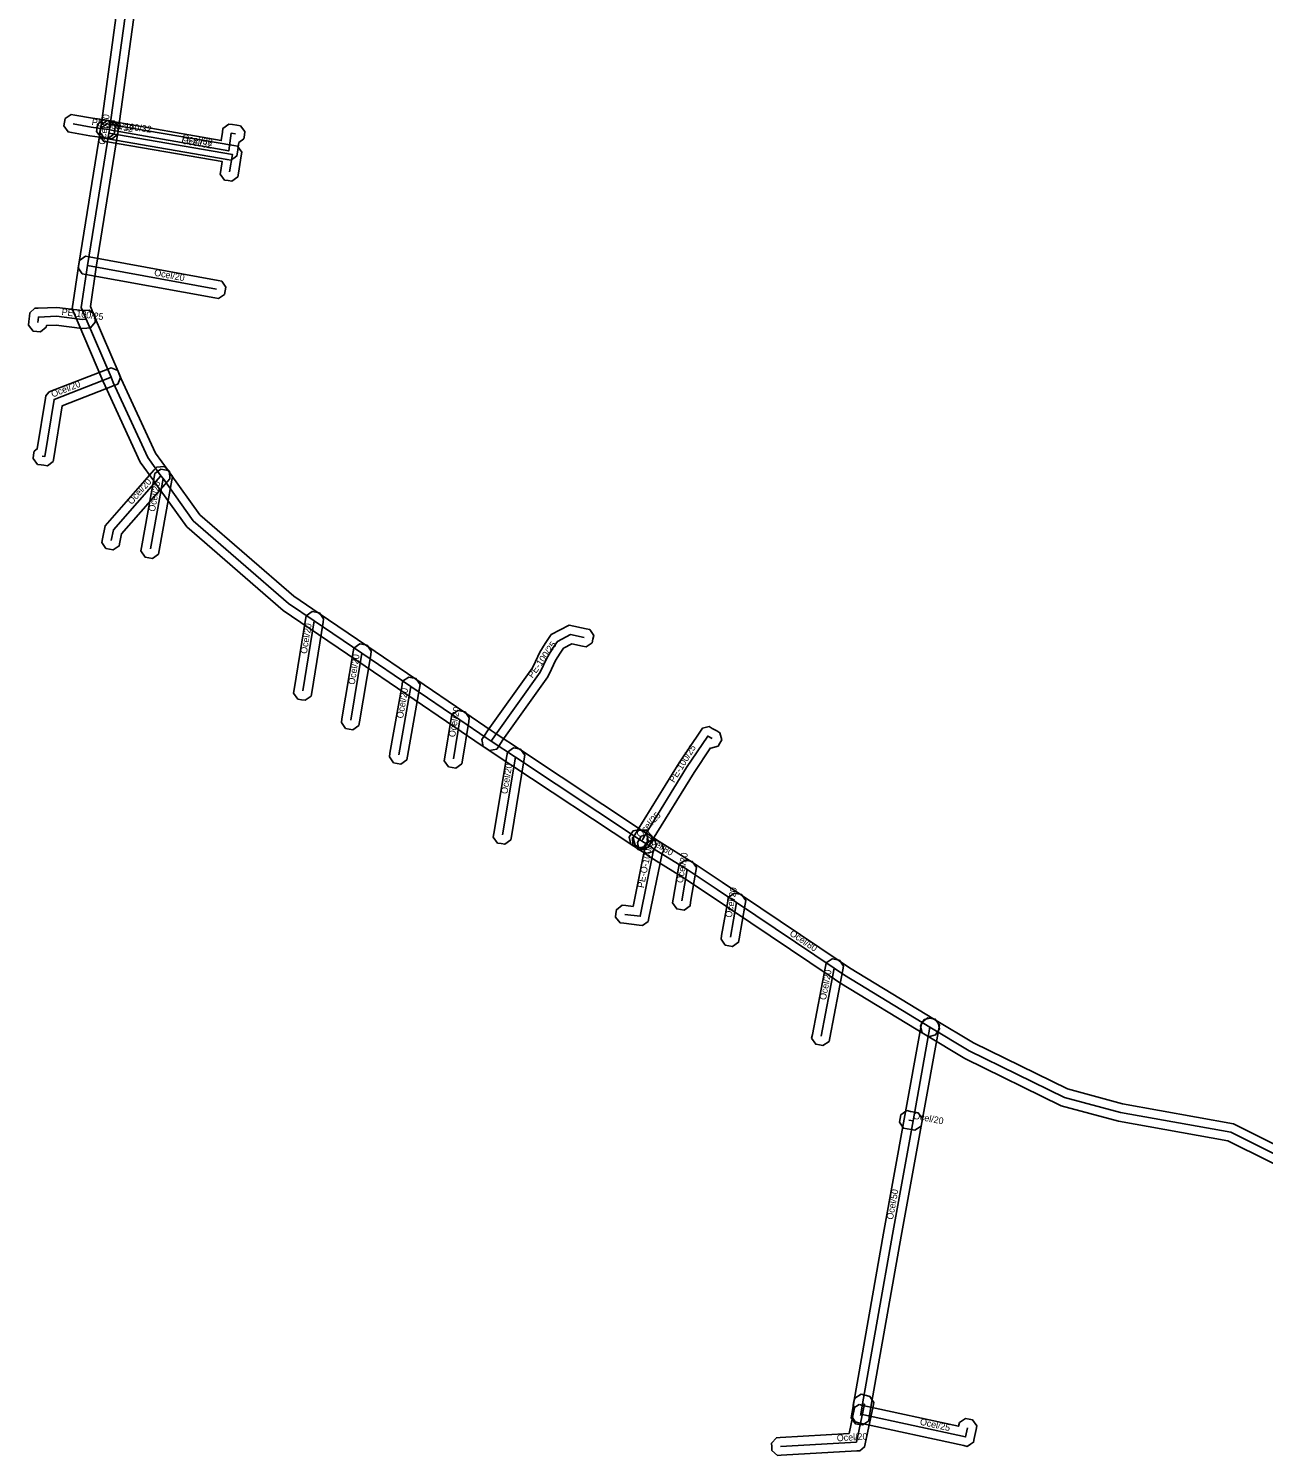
# Model space of a CAD drawing. Extents: x -569373 to -565022, y -1135090 to -1131496.
# Drawn here: x -566380.9 to -566241.6, y -1134005.2 to -1133844.4 of the extents above; entities that cross this region are included whole.
import ezdxf

# ---------------------------------------------------------------- set-up
doc = ezdxf.new("R2010")
doc.units = 0
for name, color, linetype in [('1', 7, 'Continuous'), ('24', 7, 'Continuous'), ('30', 7, 'Continuous')]:
    doc.layers.add(name, color=color, linetype=linetype)

msp = doc.modelspace()

# ---------------------------------------------------------------- linework, layer by layer
at = {"layer": '1'}
for points in [[(-566368.68, -1133840.941), (-566370.743, -1133855.926), (-566370.756, -1133855.988), (-566370.813, -1133856.339), (-566373.212, -1133871.254), (-566373.879, -1133875.691), (-566373.436, -1133876.743), (-566370.63, -1133883.289), (-566370.395, -1133883.846), (-566366.532, -1133892.224), (-566365.12, -1133894.184), (-566364.88, -1133894.514), (-566361.536, -1133899.161), (-566350.939, -1133908.356), (-566348.077, -1133910.301), (-566342.704, -1133913.951), (-566337.202, -1133917.689), (-566331.654, -1133921.459), (-566328.686, -1133923.475), (-566328.131, -1133923.853), (-566325.395, -1133925.664), (-566311.528, -1133934.846), (-566311.183, -1133935.075), (-566311.017, -1133935.887), (-566311.246, -1133936.232), (-566311.475, -1133936.577), (-566312.287, -1133936.743), (-566312.632, -1133936.514), (-566326.499, -1133927.332), (-566329.245, -1133925.513), (-566329.81, -1133925.129), (-566332.778, -1133923.113), (-566338.326, -1133919.343), (-566343.828, -1133915.605), (-566349.201, -1133911.955), (-566352.161, -1133909.944), (-566363.024, -1133900.519), (-566366.5, -1133895.686), (-566366.74, -1133895.356), (-566368.268, -1133893.236), (-566372.225, -1133884.654), (-566372.47, -1133884.071), (-566375.276, -1133877.525), (-566375.941, -1133875.949), (-566375.188, -1133870.946), (-566372.787, -1133856.021), (-566372.724, -1133855.632), (-566372.717, -1133855.594), (-566370.66, -1133840.659)], [(-566236.486, -1133974.254), (-566245.637, -1133969.709), (-566257.979, -1133967.497), (-566264.434, -1133965.75), (-566275.288, -1133960.44), (-566279.744, -1133957.768), (-566280.099, -1133957.555), (-566280.301, -1133956.751), (-566280.088, -1133956.396), (-566279.875, -1133956.041), (-566279.071, -1133955.839), (-566278.716, -1133956.052), (-566274.332, -1133958.68), (-566263.726, -1133963.87), (-566257.541, -1133965.543), (-566245.003, -1133967.791), (-566235.954, -1133972.286)]]:
    msp.add_lwpolyline(points, dxfattribs=at)
for points in [[(-566376.053, -1133854.063), (-566375.645, -1133854.135), (-566373.634, -1133854.492), (-566371.993, -1133854.719), (-566371.583, -1133854.776), (-566371.082, -1133855.437), (-566371.139, -1133855.847), (-566371.196, -1133856.257), (-566371.857, -1133856.758), (-566372.267, -1133856.701), (-566373.946, -1133856.468), (-566375.995, -1133856.105), (-566376.403, -1133856.033), (-566376.877, -1133855.353), (-566376.805, -1133854.945), (-566376.733, -1133854.537)], [(-566372.417, -1133854.667), (-566372.006, -1133854.718), (-566371.606, -1133854.768), (-566371.195, -1133854.819), (-566370.687, -1133855.473), (-566370.738, -1133855.884), (-566370.789, -1133856.295), (-566371.443, -1133856.803), (-566371.854, -1133856.752), (-566372.254, -1133856.702), (-566372.665, -1133856.651), (-566373.173, -1133855.997), (-566373.122, -1133855.586), (-566373.071, -1133855.175)], [(-566372.04, -1133855.124), (-566371.632, -1133855.194), (-566357.692, -1133857.574), (-566357.286, -1133857.643), (-566356.807, -1133858.314), (-566356.873, -1133858.72), (-566357.193, -1133860.69), (-566357.259, -1133861.099), (-566357.931, -1133861.583), (-566358.34, -1133861.517), (-566358.749, -1133861.451), (-566359.233, -1133860.779), (-566359.167, -1133860.37), (-566359.006, -1133859.379), (-566371.968, -1133857.166), (-566372.376, -1133857.096), (-566372.856, -1133856.42), (-566372.786, -1133856.012), (-566372.716, -1133855.604)], [(-566356.577, -1133856.809), (-566357.149, -1133857.24), (-566357.3, -1133858.31), (-566357.359, -1133858.73), (-566357.702, -1133858.979), (-566358.045, -1133859.228), (-566358.463, -1133859.155), (-566371.913, -1133856.795), (-566372.321, -1133856.723), (-566372.797, -1133856.045), (-566372.725, -1133855.637), (-566372.653, -1133855.229), (-566371.975, -1133854.753), (-566371.567, -1133854.825), (-566359.135, -1133857.006), (-566359, -1133856.05), (-566358.942, -1133855.64), (-566358.281, -1133855.142), (-566357.871, -1133855.2), (-566357.371, -1133855.27), (-566356.961, -1133855.327), (-566356.462, -1133855.989), (-566356.52, -1133856.399)], [(-566359.432, -1133874.819), (-566359.84, -1133874.744), (-566374.38, -1133872.084), (-566374.788, -1133872.009), (-566375.259, -1133871.328), (-566375.184, -1133870.92), (-566375.109, -1133870.512), (-566374.428, -1133870.041), (-566374.02, -1133870.116), (-566359.48, -1133872.776), (-566359.072, -1133872.851), (-566358.601, -1133873.532), (-566358.676, -1133873.94), (-566358.751, -1133874.348)], [(-566377.732, -1133877.812), (-566378.846, -1133877.856), (-566378.868, -1133878.047), (-566379.517, -1133878.562), (-566379.928, -1133878.514), (-566380.339, -1133878.466), (-566380.854, -1133877.817), (-566380.806, -1133877.406), (-566380.733, -1133876.775), (-566380.691, -1133876.408), (-566380.148, -1133875.905), (-566379.779, -1133875.891), (-566377.648, -1133875.808), (-566374.77, -1133876.165), (-566374.439, -1133876.137), (-566374.026, -1133876.103), (-566373.393, -1133876.638), (-566373.359, -1133877.051), (-566373.325, -1133877.464), (-566373.86, -1133878.097), (-566374.273, -1133878.131), (-566374.81, -1133878.175)], [(-566380.236, -1133892.018), (-566379.875, -1133891.741), (-566378.957, -1133886.022), (-566378.915, -1133885.759), (-566378.581, -1133885.345), (-566378.333, -1133885.248), (-566371.913, -1133882.748), (-566371.527, -1133882.598), (-566370.768, -1133882.931), (-566370.618, -1133883.317), (-566370.468, -1133883.703), (-566370.801, -1133884.462), (-566371.187, -1133884.612), (-566377.073, -1133886.904), (-566378.013, -1133892.758), (-566378.077, -1133893.16), (-566378.729, -1133893.645), (-566379.132, -1133893.591), (-566379.432, -1133893.551), (-566379.842, -1133893.496), (-566380.346, -1133892.838), (-566380.291, -1133892.428)], [(-566372.591, -1133902.281), (-566372.511, -1133901.875), (-566372.219, -1133900.401), (-566366.681, -1133894.109), (-566366.407, -1133893.798), (-566365.58, -1133893.746), (-566365.269, -1133894.019), (-566364.958, -1133894.293), (-566364.906, -1133895.12), (-566365.179, -1133895.431), (-566370.361, -1133901.319), (-566370.549, -1133902.265), (-566370.63, -1133902.671), (-566371.319, -1133903.131), (-566371.725, -1133903.051), (-566372.131, -1133902.97)], [(-566368.178, -1133903.25), (-566368.104, -1133902.842), (-566366.674, -1133894.922), (-566366.6, -1133894.514), (-566365.92, -1133894.042), (-566365.512, -1133894.116), (-566365.104, -1133894.19), (-566364.632, -1133894.87), (-566364.706, -1133895.278), (-566366.136, -1133903.198), (-566366.21, -1133903.606), (-566366.89, -1133904.078), (-566367.298, -1133904.004), (-566367.706, -1133903.93)], [(-566350.973, -1133919.269), (-566350.907, -1133918.86), (-566349.626, -1133910.968), (-566349.56, -1133910.559), (-566348.888, -1133910.075), (-566348.479, -1133910.141), (-566348.07, -1133910.207), (-566347.586, -1133910.879), (-566347.652, -1133911.288), (-566348.933, -1133919.18), (-566348.999, -1133919.589), (-566349.671, -1133920.073), (-566350.08, -1133920.007), (-566350.489, -1133919.941)], [(-566329.751, -1133924.48), (-566329.524, -1133924.134), (-566329.045, -1133923.405), (-566324.045, -1133916.401), (-566323.713, -1133915.699), (-566323.211, -1133914.654), (-566322.621, -1133913.679), (-566321.923, -1133912.657), (-566319.893, -1133911.608), (-566317.996, -1133912.006), (-566317.59, -1133912.091), (-566317.137, -1133912.785), (-566317.222, -1133913.19), (-566317.307, -1133913.596), (-566318.001, -1133914.049), (-566318.406, -1133913.964), (-566319.607, -1133913.712), (-566320.557, -1133914.203), (-566320.939, -1133914.761), (-566321.449, -1133915.606), (-566321.907, -1133916.561), (-566322.315, -1133917.419), (-566327.395, -1133924.535), (-566327.852, -1133925.232), (-566328.079, -1133925.578), (-566328.891, -1133925.746), (-566329.237, -1133925.519), (-566329.583, -1133925.292)], [(-566345.584, -1133922.573), (-566345.516, -1133922.165), (-566344.252, -1133914.613), (-566344.184, -1133914.205), (-566343.509, -1133913.724), (-566343.101, -1133913.792), (-566342.693, -1133913.86), (-566342.212, -1133914.535), (-566342.28, -1133914.943), (-566343.544, -1133922.495), (-566343.612, -1133922.903), (-566344.287, -1133923.384), (-566344.695, -1133923.316), (-566345.103, -1133923.248)], [(-566340.177, -1133926.434), (-566340.105, -1133926.026), (-566338.749, -1133918.342), (-566338.677, -1133917.934), (-566337.998, -1133917.459), (-566337.59, -1133917.531), (-566337.182, -1133917.603), (-566336.707, -1133918.282), (-566336.779, -1133918.69), (-566338.135, -1133926.374), (-566338.207, -1133926.782), (-566338.886, -1133927.257), (-566339.294, -1133927.185), (-566339.702, -1133927.113)], [(-566333.984, -1133926.908), (-566333.917, -1133926.499), (-566333.203, -1133922.125), (-566333.136, -1133921.716), (-566332.464, -1133921.232), (-566332.055, -1133921.299), (-566331.646, -1133921.366), (-566331.162, -1133922.038), (-566331.229, -1133922.447), (-566331.943, -1133926.821), (-566332.01, -1133927.23), (-566332.682, -1133927.714), (-566333.091, -1133927.647), (-566333.5, -1133927.58)], [(-566303.924, -1133925.463), (-566303.972, -1133925.435), (-566305.829, -1133928.201), (-566310.52, -1133935.811), (-566310.752, -1133936.216), (-566310.957, -1133936.576), (-566311.756, -1133936.793), (-566312.116, -1133936.588), (-566312.476, -1133936.383), (-566312.693, -1133935.584), (-566312.488, -1133935.224), (-566312.24, -1133934.789), (-566307.511, -1133927.119), (-566305.11, -1133923.543), (-566304.89, -1133923.215), (-566304.12, -1133923.037), (-566303.778, -1133923.235), (-566303.278, -1133923.525), (-566302.92, -1133923.733), (-566302.707, -1133924.534), (-566302.915, -1133924.892), (-566303.123, -1133925.25)], [(-566328.464, -1133935.483), (-566328.396, -1133935.075), (-566326.933, -1133926.333), (-566326.865, -1133925.925), (-566326.19, -1133925.444), (-566325.782, -1133925.512), (-566325.374, -1133925.58), (-566324.893, -1133926.255), (-566324.961, -1133926.663), (-566326.424, -1133935.405), (-566326.492, -1133935.813), (-566327.167, -1133936.294), (-566327.575, -1133936.226), (-566327.983, -1133936.158)], [(-566311.885, -1133934.615), (-566311.537, -1133934.84), (-566311.203, -1133935.057), (-566310.619, -1133935.423), (-566310.268, -1133935.643), (-566310.083, -1133936.45), (-566310.303, -1133936.801), (-566310.523, -1133937.152), (-566311.33, -1133937.337), (-566311.681, -1133937.117), (-566312.277, -1133936.743), (-566312.623, -1133936.52), (-566312.971, -1133936.295), (-566313.145, -1133935.485), (-566312.92, -1133935.137), (-566312.695, -1133934.789)], [(-566312.756, -1133935.526), (-566312.62, -1133935.379), (-566312.62, -1133935.306), (-566312.034, -1133934.72), (-566311.62, -1133934.72), (-566311.206, -1133934.72), (-566310.62, -1133935.306), (-566310.62, -1133935.72), (-566310.62, -1133936.161), (-566311.005, -1133936.578), (-566311.286, -1133936.882), (-566312.114, -1133936.916), (-566312.418, -1133936.635), (-566312.722, -1133936.354)], [(-566309.25, -1133936.989), (-566309.434, -1133937.295), (-566309.441, -1133937.33), (-566310.92, -1133944.599), (-566310.998, -1133944.98), (-566311.627, -1133945.438), (-566312.014, -1133945.393), (-566313.754, -1133945.193), (-566314.166, -1133945.146), (-566314.681, -1133944.497), (-566314.633, -1133944.086), (-566314.586, -1133943.674), (-566313.937, -1133943.159), (-566313.526, -1133943.207), (-566312.697, -1133943.302), (-566311.401, -1133936.93), (-566311.325, -1133936.562), (-566311.177, -1133936.316), (-566310.964, -1133935.961), (-566310.161, -1133935.76), (-566309.806, -1133935.973), (-566309.451, -1133936.186)], [(-566279.396, -1133957.979), (-566279.75, -1133957.764), (-566289.389, -1133951.893), (-566290.587, -1133951.091), (-566301.607, -1133943.691), (-566303.786, -1133942.231), (-566307.142, -1133939.99), (-566310.875, -1133937.663), (-566311.332, -1133937.338), (-566311.684, -1133937.115), (-566312.034, -1133936.894), (-566312.217, -1133936.086), (-566311.995, -1133935.736), (-566311.774, -1133935.386), (-566310.966, -1133935.203), (-566310.616, -1133935.425), (-566310.218, -1133935.676), (-566309.765, -1133935.997), (-566306.058, -1133938.31), (-566302.674, -1133940.569), (-566300.493, -1133942.029), (-566289.473, -1133949.429), (-566288.311, -1133950.207), (-566278.71, -1133956.056), (-566278.356, -1133956.271), (-566278.161, -1133957.076), (-566278.376, -1133957.43), (-566278.591, -1133957.784)], [(-566308.256, -1133942.9), (-566308.186, -1133942.492), (-566307.586, -1133938.982), (-566307.516, -1133938.574), (-566306.84, -1133938.094), (-566306.432, -1133938.164), (-566306.024, -1133938.234), (-566305.544, -1133938.91), (-566305.614, -1133939.318), (-566306.214, -1133942.828), (-566306.284, -1133943.236), (-566306.96, -1133943.716), (-566307.368, -1133943.646), (-566307.776, -1133943.576)], [(-566302.786, -1133946.996), (-566302.715, -1133946.588), (-566302.035, -1133942.688), (-566301.964, -1133942.28), (-566301.286, -1133941.804), (-566300.878, -1133941.875), (-566300.47, -1133941.946), (-566299.994, -1133942.624), (-566300.065, -1133943.032), (-566300.745, -1133946.932), (-566300.816, -1133947.34), (-566301.494, -1133947.816), (-566301.902, -1133947.745), (-566302.31, -1133947.674)], [(-566292.571, -1133958.137), (-566292.492, -1133957.73), (-566291.012, -1133950.07), (-566290.933, -1133949.663), (-566290.247, -1133949.199), (-566289.84, -1133949.278), (-566289.433, -1133949.357), (-566288.969, -1133950.043), (-566289.048, -1133950.45), (-566290.528, -1133958.11), (-566290.607, -1133958.517), (-566291.293, -1133958.981), (-566291.7, -1133958.902), (-566292.107, -1133958.823)], [(-566278.172, -1133956.68), (-566278.246, -1133957.088), (-566280.156, -1133967.638), (-566282.486, -1133980.456), (-566285.845, -1133999.512), (-566286.044, -1134000.658), (-566286.074, -1134000.834), (-566286.142, -1134001.243), (-566286.816, -1134001.724), (-566287.224, -1134001.656), (-566287.633, -1134001.588), (-566288.114, -1134000.914), (-566288.046, -1134000.506), (-566288.016, -1134000.322), (-566287.815, -1133999.168), (-566284.454, -1133980.104), (-566282.124, -1133967.282), (-566280.214, -1133956.732), (-566280.14, -1133956.324), (-566279.46, -1133955.852), (-566279.052, -1133955.926), (-566278.644, -1133956)], [(-566280.921, -1133968.52), (-566281.328, -1133968.442), (-566281.798, -1133968.352), (-566282.205, -1133968.274), (-566282.67, -1133967.589), (-566282.592, -1133967.182), (-566282.514, -1133966.775), (-566281.829, -1133966.31), (-566281.422, -1133966.388), (-566280.952, -1133966.478), (-566280.545, -1133966.556), (-566280.08, -1133967.241), (-566280.158, -1133967.648), (-566280.236, -1133968.055)], [(-566288.342, -1134002.705), (-566287.733, -1133999.78), (-566287.901, -1133999.499), (-566287.8, -1133999.097), (-566287.7, -1133998.695), (-566286.989, -1133998.269), (-566286.587, -1133998.37), (-566286.387, -1133998.42), (-566285.997, -1133998.518), (-566285.569, -1133999.2), (-566285.651, -1133999.594), (-566286.541, -1134003.864), (-566286.61, -1134004.196), (-566287.125, -1134004.639), (-566287.464, -1134004.658), (-566296.014, -1134005.138), (-566296.427, -1134005.161), (-566297.045, -1134004.609), (-566297.068, -1134004.196), (-566297.091, -1134003.783), (-566296.539, -1134003.165), (-566296.126, -1134003.142)], [(-566287.222, -1133999.425), (-566286.817, -1133999.513), (-566276.005, -1134001.875), (-566276.001, -1134001.858), (-566275.921, -1134001.451), (-566275.234, -1134000.989), (-566274.828, -1134001.069), (-566274.421, -1134001.149), (-566273.959, -1134001.836), (-566274.039, -1134002.242), (-566274.239, -1134003.262), (-566274.32, -1134003.675), (-566274.671, -1134003.906), (-566275.023, -1134004.137), (-566275.433, -1134004.047), (-566287.243, -1134001.467), (-566287.648, -1134001.379), (-566288.095, -1134000.682), (-566288.007, -1134000.277), (-566287.919, -1133999.872)]]:
    msp.add_lwpolyline(points, close=True, dxfattribs=at)
at = {"layer": '24'}
for points in [[(-566312.08, -1133935.68), (-566325.947, -1133926.498), (-566328.688, -1133924.683), (-566329.248, -1133924.302), (-566332.216, -1133922.286), (-566337.764, -1133918.516), (-566343.266, -1133914.778), (-566348.639, -1133911.128), (-566351.55, -1133909.15), (-566362.28, -1133899.84), (-566365.69, -1133895.1), (-566365.93, -1133894.77), (-566367.4, -1133892.73), (-566371.31, -1133884.25), (-566371.55, -1133883.68), (-566374.356, -1133877.134), (-566374.91, -1133875.82), (-566374.2, -1133871.1), (-566371.8, -1133856.18), (-566371.74, -1133855.81), (-566371.73, -1133855.76), (-566369.67, -1133840.8)], [(-566375.82, -1133855.12), (-566373.79, -1133855.48), (-566372.13, -1133855.71)], [(-566372.13, -1133855.71), (-566371.73, -1133855.76)], [(-566371.8, -1133856.18), (-566357.86, -1133858.56), (-566358.18, -1133860.53)], [(-566357.51, -1133856.26), (-566358.01, -1133856.19), (-566358.29, -1133858.17), (-566371.74, -1133855.81)], [(-566359.66, -1133873.76), (-566374.2, -1133871.1)], [(-566379.813, -1133877.521), (-566379.74, -1133876.89), (-566377.69, -1133876.81), (-566374.79, -1133877.17), (-566374.356, -1133877.134)], [(-566379.3, -1133892.56), (-566379, -1133892.6), (-566377.97, -1133886.18), (-566371.55, -1133883.68)], [(-566371.53, -1133902.07), (-566371.29, -1133900.86), (-566365.93, -1133894.77)], [(-566367.12, -1133903.02), (-566365.69, -1133895.1)], [(-566349.92, -1133919.02), (-566348.639, -1133911.128)], [(-566328.688, -1133924.683), (-566328.22, -1133923.97), (-566323.18, -1133916.91), (-566322.81, -1133916.13), (-566322.33, -1133915.13), (-566321.78, -1133914.22), (-566321.24, -1133913.43), (-566319.75, -1133912.66), (-566318.201, -1133912.985)], [(-566344.53, -1133922.33), (-566343.266, -1133914.778)], [(-566339.12, -1133926.2), (-566337.764, -1133918.516)], [(-566332.93, -1133926.66), (-566332.216, -1133922.286)], [(-566303.78, -1133924.39), (-566304.28, -1133924.1), (-566306.67, -1133927.66), (-566311.38, -1133935.3), (-566311.62, -1133935.72)], [(-566327.41, -1133935.24), (-566325.947, -1133926.498)], [(-566312.08, -1133935.68), (-566311.74, -1133935.9), (-566311.15, -1133936.27)], [(-566311.62, -1133935.72), (-566311.62, -1133935.77), (-566311.74, -1133935.9)], [(-566279.23, -1133956.91), (-566288.85, -1133951.05), (-566290.03, -1133950.26), (-566301.05, -1133942.86), (-566303.23, -1133941.4), (-566306.6, -1133939.15), (-566310.32, -1133936.83), (-566310.775, -1133936.507), (-566311.15, -1133936.27)], [(-566310.32, -1133936.83), (-566310.38, -1133936.93), (-566310.421, -1133937.13), (-566311.9, -1133944.4), (-566313.64, -1133944.2)], [(-566307.2, -1133942.66), (-566306.6, -1133939.15)], [(-566301.73, -1133946.76), (-566301.05, -1133942.86)], [(-566291.51, -1133957.92), (-566290.03, -1133950.26)], [(-566169.63, -1133951.26), (-566184.16, -1133959.22), (-566192.59, -1133962.32), (-566198.44, -1133964.47), (-566204, -1133964.21), (-566213.72, -1133968.02), (-566224.56, -1133972.51), (-566225.88, -1133973.06), (-566229.69, -1133973.71), (-566233.56, -1133973.45), (-566236.22, -1133973.27), (-566245.32, -1133968.75), (-566257.76, -1133966.52), (-566264.08, -1133964.81), (-566274.81, -1133959.56), (-566279.23, -1133956.91)], [(-566279.23, -1133956.91), (-566281.14, -1133967.46), (-566283.47, -1133980.28), (-566286.83, -1133999.34), (-566287.03, -1134000.49), (-566287.06, -1134000.67)], [(-566281.14, -1133967.46), (-566281.61, -1133967.37)], [(-566296.07, -1134004.14), (-566287.52, -1134003.66), (-566286.63, -1133999.39), (-566286.83, -1133999.34)], [(-566287.03, -1134000.49), (-566275.22, -1134003.07), (-566275.02, -1134002.05)]]:
    msp.add_lwpolyline(points, dxfattribs=at)

# ---------------------------------------------------------------- texts
at = {"layer": '30'}
for s, rotation, p in [('PE-100/32', 349.94372, (-566373.78, -1133855.246)), ('Ocel/80', 80.8618, (-566372.246, -1133857.512)), ('PE-100/32', 352.87498, (-566371.73, -1133855.535)), ('Ocel/32', 350.04792, (-566363.582, -1133857.006)), ('Ocel/32', 350.31121, (-566363.646, -1133857.338)), ('Ocel/20', 349.63275, (-566366.73, -1133872.23)), ('PE-100/25', 352.92362, (-566377.157, -1133876.651)), ('Ocel/20', 21.27634, (-566378.13, -1133885.965)), ('Ocel/20', 48.64798, (-566369.218, -1133898.078)), ('Ocel/20', 79.7652, (-566366.605, -1133898.86)), ('Ocel/20', 80.78037, (-566349.48, -1133914.874)), ('PE-100/25', 54.47768, (-566324.041, -1133917.636)), ('Ocel/20', 80.49831, (-566344.098, -1133918.354)), ('Ocel/20', 79.99202, (-566338.642, -1133922.158)), ('Ocel/20', 80.72896, (-566332.773, -1133924.273)), ('PE-100/25', 58.34649, (-566308.075, -1133929.415)), ('Ocel/20', 80.49942, (-566326.878, -1133930.669)), ('Ocel/25', 47.29061, (-566311.863, -1133935.617)), ('PE-O-100/32', 78.50074, (-566311.503, -1133941.266)), ('Ocel/80', 327.90741, (-566311.374, -1133935.804)), ('Ocel/20', 80.29961, (-566307.1, -1133940.705)), ('Ocel/20', 80.1094, (-566301.59, -1133944.61)), ('Ocel/80', 326.11839, (-566295.123, -1133946.506)), ('Ocel/20', 79.06454, (-566290.97, -1133953.89)), ('Ocel/20', 349.15969, (-566281.175, -1133967.215)), ('Ocel/50', 79.69909, (-566283.406, -1133978.63)), ('Ocel/25', 347.67683, (-566280.417, -1134001.691)), ('Ocel/20', 3.21323, (-566289.715, -1134003.572))]:
    msp.add_text(s, height=0.75, rotation=rotation, dxfattribs=at).set_placement(p)

doc.saveas('drawing.dxf')
